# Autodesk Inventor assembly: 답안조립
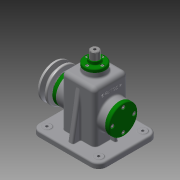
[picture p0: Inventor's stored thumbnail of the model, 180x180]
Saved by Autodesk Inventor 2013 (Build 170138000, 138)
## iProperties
Created: 2016-01
Part Number: 답안조립
Document SubType Name: Assembly
Designer: Administrator
Author: Administrator
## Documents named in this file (19)
- C:\Users\Administrator\Desktop\460127V1001\답안조립.iam
- C:\Users\Administrator\Desktop\460127V1001\1본체.ipt
- C:\Users\Administrator\Desktop\460127V1001\V-벨트풀리.ipt
- C:\Users\Administrator\Desktop\460127V1001\고정핀.ipt
- C:\Users\Administrator\Desktop\460127V1001\뒤커버.ipt
- C:\Users\Administrator\Desktop\460127V1001\링크.ipt
- C:\Users\Administrator\Desktop\460127V1001\멈춤링 6 x 5.ipt
- C:\Users\Administrator\Desktop\460127V1001\멈춤링 15 x 1.ipt
- C:\Users\Administrator\Desktop\460127V1001\베어링 15 x 35 x 11.ipt
- C:\Users\Administrator\Desktop\460127V1001\볼트 M3 x 8.ipt
- C:\Users\Administrator\Desktop\460127V1001\볼트 M4 x 10.ipt
- C:\Users\Administrator\Desktop\460127V1001\볼트 M6 x 12.ipt
- C:\Users\Administrator\Desktop\460127V1001\상부부시.ipt
- C:\Users\Administrator\Desktop\460127V1001\슬라이드바.ipt
- C:\Users\Administrator\Desktop\460127V1001\앞커버.ipt
- C:\Users\Administrator\Desktop\460127V1001\오일실 15 25 7.ipt
- C:\Users\Administrator\Desktop\460127V1001\와셔.ipt
- C:\Users\Administrator\Desktop\460127V1001\키 5 x 5 x 14.ipt
- C:\Users\Administrator\Desktop\460127V1001\편심축.ipt
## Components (16 placed, 6 different names)
1. 1본체:1
2. V-벨트풀리:1 — 각도:2
3. 고정핀:1
4. ISO 4018 M6 x 12:1
5. ISO 4762 M4 x 10:1
6. ISO 4762 M4 x 10:3
7. ISO 4762 M4 x 10:4
8. ISO 4762 M4 x 10:5
9. ISO 4762 M4 x 10:2
10. ISO 4762 M4 x 10:6
11. ISO 4762 M4 x 10:7
12. ISO 4762 M4 x 10:8
13. ISO 4762 M3 x 8:1
14. ISO 4762 M3 x 8:2
15. ISO 4762 M3 x 8:3
16. ISO 4762 M3 x 8:4
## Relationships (1: Angle 1)
- 각도:2 [Angle]: V-벨트풀리:1
